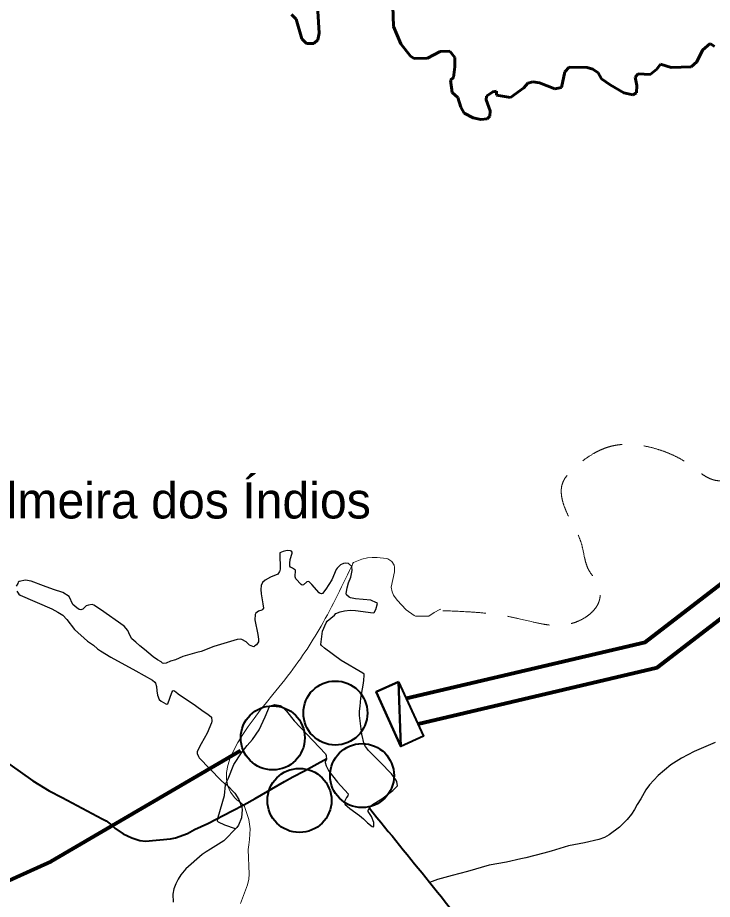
# Model space of a CAD drawing. Extents: x 553962 to 842807, y 8883888 to 9032388.
# Drawn here: x 756667 to 766307, y 8955756 to 8967998 of the extents above; entities that cross this region are included whole.
import ezdxf

# ---------------------------------------------------------------- set-up
doc = ezdxf.new("R2010")
doc.units = 0
doc.header["$LTSCALE"] = 200
doc.linetypes.add('LONG_DASH_SHORT_DASH', pattern=[9.9, 6, -1.2, 1.5, -1.2])
doc.linetypes.add('MEDIUM_DASHED', pattern=[4.5, 3, -1.5])
for name, color, linetype, lineweight in [('12', 7, 'Continuous', 25), ('14', 7, 'Continuous', 13), ('21', 7, 'Continuous', 25), ('28', 7, 'Continuous', 40), ('41', 7, 'Continuous', 40), ('7', 7, 'LONG_DASH_SHORT_DASH', 60)]:
    doc.layers.add(name, color=color, linetype=linetype, lineweight=lineweight)

msp = doc.modelspace()

# ---------------------------------------------------------------- linework, layer by layer
at = {"layer": '12', "lineweight": 40}
for points in [[(755751.2, 8958147.5), (755862.2, 8958064), (755958, 8957996.2), (756032.6, 8957954.2), (756137.7, 8957884), (756214, 8957842.6), (756328.1, 8957767.5), (756559.2, 8957627.5), (756879.8, 8957401.3), (757104, 8957264.6), (757287.1, 8957167.7), (757840.4, 8956875)], [(759805, 8957070.3), (759963.8, 8957157.4), (760368.2, 8957393.4), (760487, 8957457.4), (760649.4, 8957537.9), (760959, 8957710.3)], [(757840.4, 8956875), (757898, 8956844.5), (757957.3, 8956800.7), (758017.3, 8956746), (758132.8, 8956665.6), (758252.6, 8956612), (758364.7, 8956572), (758441.3, 8956562.7), (758786.4, 8956593.9), (758858.3, 8956611.9), (759022.3, 8956672.3), (759120.5, 8956724.4), (759308, 8956809.8), (759644.5, 8956982.5), (759805, 8957070.3)]]:
    msp.add_lwpolyline(points, dxfattribs=at)
at = {"layer": '12'}
for points in [[(766345.4, 8957933.7), (766056.1, 8957810.9), (766056.1, 8957810.9), (765878.8, 8957715.7), (765733, 8957623.3), (765557.2, 8957477.4), (765435.6, 8957344.7), (765384.6, 8957275.8), (765313.5, 8957149.9), (765262.4, 8957073.2), (765227, 8957004.6), (765185.1, 8956938.5), (765125.7, 8956864.1), (765018.7, 8956759.9), (764877.3, 8956651.4), (764811.5, 8956613.4), (764731.2, 8956586.7), (764533.1, 8956539.3), (764309.6, 8956500.2), (764071.8, 8956426.7)], [(759689.9, 8956732.7), (759543.3, 8956787), (759453.4, 8956827.9), (759441.1, 8956839.4), (759450.5, 8956898), (759538.2, 8957195.8), (759549.6, 8957346.3), (759553.3, 8957357.9), (759571, 8957344.3), (759680.6, 8957229.9), (759737, 8957142.1), (759777.6, 8957031.5), (759780.6, 8957004.8), (759774.7, 8956889.8), (759729.9, 8956785.1), (759706.9, 8956753.4), (759526.3, 8956568.6), (759344.8, 8956450.4), (759284.8, 8956417.4), (759226.1, 8956377.1), (758999, 8956178.4), (758931.1, 8956094.6), (758894, 8956037.2), (758861.3, 8955972.4), (758835.9, 8955899.8), (758821.1, 8955826.8), (758825.4, 8955718.1)], [(764071.8, 8956426.7), (763971, 8956395.5), (763720.5, 8956331.2), (763648.1, 8956319.8), (763449.9, 8956272.7), (763209, 8956229.3), (762911.9, 8956140.7), (762698.3, 8956084.6)], [(762698.3, 8956084.6), (762494.3, 8956031.1), (762382.1, 8955988.1)]]:
    msp.add_lwpolyline(points, dxfattribs=at)
at = {"layer": '12', "lineweight": 40}
msp.add_spline([(761549.2, 8957020.4), (762383.1, 8955993.9), (763257, 8954902.9), (764214.4, 8953717.3), (766168.2, 8951324.4), (767086.6, 8950171.6), (770317.8, 8946184.2), (771971, 8944146), (773006.3, 8942876.2), (773223.4, 8942642.3), (773373.7, 8942274.8), (774008.3, 8940921.5), (774359, 8940136.3), (774475.8, 8939919.1), (774642.8, 8939785.5), (774893.3, 8939668.5), (775511.2, 8939484.7), (775928.6, 8939267.5), (776078.9, 8939184), (776379.5, 8938916.7), (776680.1, 8938749.6), (776830.4, 8938582.6), (777398.1, 8938348.7), (777899.1, 8938231.7), (778550.4, 8938482.3), (779134.8, 8938866.6), (779452.1, 8939250.8), (779569, 8939384.5), (779685.9, 8939351.1), (779852.9, 8939217.4), (780086.7, 8939217.4), (780604.3, 8939451.3), (781055.2, 8939618.4), (781439.3, 8939618.4), (781823.3, 8939518.1), (782090.5, 8939401.2), (782290.9, 8939367.8), (782524.7, 8939518.1), (782858.7, 8939618.4), (783192.6, 8939651.8), (783509.9, 8939818.9), (783910.7, 8940119.6), (784278.1, 8940336.8), (784625.2, 8940434.5)], degree=3, dxfattribs=at)
at = {"layer": '14'}
for points in [[(762539, 8959785.5), (762526.5, 8959782.1), (762447.5, 8959737.2), (762371.9, 8959688.1), (762188, 8959687.4), (762169, 8959695.8), (762058.2, 8959775.3), (761932.6, 8959909.4), (761880.9, 8959981.3), (761863.6, 8960025), (761852.7, 8960090.2), (761896.3, 8960301.7), (761898.2, 8960370.1), (761891.8, 8960394.3), (761858.6, 8960446.3), (761803.1, 8960482.1), (761785, 8960487.6), (761657.6, 8960503.3), (761588.8, 8960503.3), (761520, 8960497.3), (761442.8, 8960481.4), (761326.7, 8960433.8), (761317.3, 8960424.7), (761303.1, 8960378.2)], [(759805, 8957070.3), (759809.7, 8957060.9), (759876.2, 8956866.7), (759896, 8956733.5), (759886, 8956587.7), (759873.4, 8956514.6), (759867.3, 8956445.9), (759879.8, 8956106.2), (759877.3, 8956037.4), (759858.6, 8955956.3), (759761.5, 8955697.4)]]:
    msp.add_lwpolyline(points, dxfattribs=at)
at = {"layer": '14', "linetype": 'MEDIUM_DASHED'}
msp.add_spline([(762566.7, 8959763.7), (763408.4, 8959695.8), (763753.5, 8959622.6), (764114.2, 8959559.8), (764542.9, 8959669.6), (764741.6, 8959915.3), (764720.7, 8960129.7), (764595.2, 8960323.1), (764490.6, 8960694.3), (764312.9, 8961070.7), (764229.2, 8961536), (764396.5, 8961750.3), (764929.8, 8962053.6), (765541.5, 8962006.5), (766027.7, 8961766), (766283.8, 8961593.5), (766466.8, 8961577.8), (766618.4, 8961776.5), (766670.7, 8962090.2), (766874.6, 8962247), (767287.6, 8962158.1), (767324.2, 8962132)], degree=3, dxfattribs=at)
at = {"layer": '14'}
msp.add_spline([(761326.7, 8960433.8), (760878.8, 8959550), (760374.9, 8958805.9), (759682, 8957166.3), (759809.7, 8957060.9)], degree=3, dxfattribs=at)
at = {"layer": '21'}
for points in [[(760406.9, 8960599.4), (760351.2, 8960587.4), (760306.3, 8960567.9), (760304.1, 8960553.3), (760309.9, 8960343.7), (760307.6, 8960319.4), (760302.3, 8960306.5), (760277, 8960272.3), (760173.9, 8960227.9), (760102, 8960186.9), (760066.3, 8960155.5), (760048.5, 8960114.9), (760043.8, 8960055.7), (760047.2, 8959999.8), (760070.9, 8959859.8), (760077.3, 8959796.6), (760071.9, 8959782.9), (760055.5, 8959771.5), (760010.4, 8959755.9), (759970.5, 8959727.7), (759962.7, 8959712), (759957.3, 8959636.2), (760000.3, 8959433.2), (760011.1, 8959366.6), (760007.5, 8959329.7), (759980.1, 8959288.4), (759957.5, 8959276), (759943.8, 8959263.8), (759943.8, 8959263.8), (759931.4, 8959264.6), (759884.8, 8959286.2), (759838.1, 8959329.8), (759780.4, 8959363), (759763.1, 8959366.1), (759715.1, 8959363.1), (759387.5, 8959268.5), (759215.8, 8959195.5), (759154.3, 8959182.2), (759089.3, 8959164.5)], [(761303.1, 8960378.2), (761256.6, 8960420.7), (761211, 8960424.4), (761189, 8960420), (761148.3, 8960398.4), (761101, 8960352.7), (761089.5, 8960334.7), (761027.1, 8960191.2), (760943.1, 8960062.8), (760896.2, 8960002.8), (760882, 8959997.4), (760865.7, 8960003.5), (760853.2, 8960013.2), (760749.8, 8960127.6), (760712.2, 8960164.5), (760701.2, 8960167.6), (760679.8, 8960164.2), (760632.4, 8960121), (760616.8, 8960117.8), (760603.7, 8960126.1), (760526.3, 8960205.6), (760516.4, 8960233.9), (760520.7, 8960327.1), (760483.2, 8960353), (760453.9, 8960367.2), (760443.7, 8960384.1), (760443.7, 8960422.2), (760450.8, 8960474.1), (760476.4, 8960562.9), (760474.8, 8960577.8), (760467.9, 8960589.4), (760454.3, 8960595.3), (760406.9, 8960599.4)], [(761456.2, 8958896.2), (761158.8, 8959073.4), (760923.1, 8959244.1), (760881.8, 8959278.4), (760874.4, 8959292.7), (760897, 8959480.3), (760948.2, 8959595.3), (760963.9, 8959617.7), (761063.1, 8959703.5), (761082.5, 8959724.5), (761142.1, 8959747.5), (761202.2, 8959763.2), (761279.4, 8959770.2), (761356.4, 8959765.7), (761602.1, 8959732.9), (761613.8, 8959740.5), (761636.1, 8959780.9), (761661.5, 8959862.7), (761646.6, 8959874.6), (761567.3, 8959909.9), (761356.6, 8959929.5), (761288, 8959941.5), (761269.3, 8959950.7), (761230.4, 8959983.8), (761227.4, 8960000.2), (761237.8, 8960082), (761258.1, 8960151), (761288.7, 8960228.4), (761310.4, 8960320.3), (761303.1, 8960378.2)], [(756667.8, 8960142.8), (756646.1, 8960103.2)], [(757025.3, 8960111), (756856.9, 8960173.6), (756774.4, 8960189), (756690.4, 8960169.5), (756676.8, 8960159.2), (756667.8, 8960142.8)], [(757384.3, 8959963), (757296.5, 8960017), (757165.6, 8960058.9), (757025.3, 8960111)], [(756655.4, 8960034.6), (756685.1, 8959993.4), (756700.1, 8959979.2), (757143.4, 8959788.8), (757225.5, 8959744.8), (757292.5, 8959702.4), (757351, 8959642), (757458.4, 8959500.5), (757638.5, 8959341.8), (757717.9, 8959284.2), (757774.1, 8959233.8), (757815.6, 8959204.4), (757958.2, 8959117.6), (758306, 8958929.9), (758539.4, 8958798.4), (758570.9, 8958770.5), (758581.6, 8958755.2), (758594, 8958710.9), (758597.7, 8958651.4), (758608.3, 8958591.8), (758630.7, 8958530.3), (758658.3, 8958506.6), (758722.6, 8958472.6), (758739.5, 8958467.4), (758749.1, 8958469.2), (758804.9, 8958627.7), (758819.6, 8958652.9), (758832.5, 8958653.7), (758862.6, 8958638.9), (758895.1, 8958607.2), (759137.6, 8958446.3), (759240.8, 8958367.8), (759305.9, 8958326.1), (759355.4, 8958284.4), (759361.1, 8958229.7), (759356.1, 8958207.5), (759296.4, 8958064.8), (759214.4, 8957916.7), (759160.7, 8957806.5), (759158.7, 8957795.2)], [(759089.3, 8959164.5), (758959.7, 8959128.9), (758856.5, 8959082.7), (758786.4, 8959061), (758729.8, 8959035.8), (758696.2, 8959030.6), (758679.5, 8959033.6), (758657.5, 8959052.8), (758608.3, 8959079.4), (758549.1, 8959121.3), (758427, 8959226.7), (758365.1, 8959274.5), (758308.6, 8959327.6), (758250.8, 8959371), (758222.4, 8959421.7), (758194.1, 8959488.8), (758147.7, 8959547.5), (757819.2, 8959780.1), (757726.2, 8959841.5), (757701.7, 8959847.4), (757651.1, 8959840.7), (757620.3, 8959829.3), (757571.8, 8959784.6), (757543.6, 8959777.7), (757522.3, 8959779.8), (757486.6, 8959802), (757431.8, 8959850.2), (757384.3, 8959963)], [(761460.2, 8958729), (761471.4, 8958793.2), (761478, 8958868), (761475.3, 8958881.2), (761456.2, 8958896.2)], [(761699.8, 8957660.8), (761534.4, 8957820.5), (761494.3, 8957876.1), (761476.7, 8957908.7), (761441.7, 8958050.3), (761410.2, 8958307.4), (761410.3, 8958367.7), (761421.6, 8958439.5), (761428.9, 8958549.5), (761460.2, 8958729)], [(759588.1, 8957430.5), (759665.6, 8957627.1), (759774.1, 8957789.3), (759851, 8957889.6), (759926.4, 8957977.2), (760019.3, 8958109.5), (760103.6, 8958290.5), (760163.1, 8958434.3), (760177, 8958444.1), (760236, 8958459.9), (760236, 8958459.9), (760311.5, 8958445.7), (760328.1, 8958437.3), (760399.4, 8958368.9), (760505.5, 8958234.5), (760941.1, 8957774.4), (760949.2, 8957754.5), (760953.1, 8957699.6), (760934.3, 8957666.8), (760932.5, 8957654.1), (760946.9, 8957611.2), (760983.8, 8957536.8), (761107.8, 8957384.2), (761255, 8957220.4), (761250.7, 8957192.7), (761230.3, 8957168.3), (761203.2, 8957115.4), (761200.8, 8957095.3), (761208, 8957075.8), (761277.5, 8957017.6), (761412.8, 8956919.4), (761466, 8956875.3), (761523.6, 8956817.2), (761588.2, 8956767.8), (761600.9, 8956762.8), (761607.8, 8956766.9), (761610.8, 8956824.1), (761578.4, 8956906.9), (761533.3, 8956976.3), (761532.5, 8956989.4), (761545, 8957020.8), (761589.6, 8957073.6), (761719.9, 8957149.7), (761874.4, 8957269.1), (761925.5, 8957315.7), (761936.7, 8957332.9), (761927.8, 8957389.9), (761916.5, 8957416.7), (761854.4, 8957499), (761699.8, 8957660.8)], [(759158.7, 8957795.2), (759156.5, 8957782.8), (759174.7, 8957739.3), (759187.4, 8957722), (759486.6, 8957410.7), (759541.3, 8957360.2), (759547, 8957358.6), (759554, 8957364.5), (759569.1, 8957391.3), (759588.1, 8957430.5)]]:
    msp.add_lwpolyline(points, dxfattribs=at)
at = {"layer": '28', "lineweight": 80}
for p, q in [((759759.2, 8957818.1), (757134.6, 8956280.5)), ((757134.6, 8956280.5), (754888.4, 8955266.6))]:
    msp.add_line(p, q, dxfattribs=at)
for points in [[(762063.2, 8958548.7), (765372.8, 8959328.2), (767563.5, 8961012.7), (769365.7, 8961826.5), (770195.5, 8963207.4)], [(762225.3, 8958192.4), (765541.3, 8958973.5), (767762.1, 8960681.2), (769633, 8961525.9), (770439.4, 8962868)]]:
    msp.add_lwpolyline(points, dxfattribs=at)
at = {"layer": '28'}
msp.add_lwpolyline([(761954, 8958776.7), (762297, 8958021.1), (761985.7, 8957879.8), (761642.7, 8958635.3)], close=True, dxfattribs=at)
for points in [[(761954, 8958776.7), (761642.7, 8958635.3), (761985.7, 8957879.8)], [(761954, 8958776.7), (761985.7, 8957879.8), (761954, 8958776.7)]]:
    msp.add_lwpolyline(points, dxfattribs=at)
for centre in [(761076.3, 8958343), (760207.7, 8957997.9), (761446.7, 8957473.9), (760578.1, 8957128.8)]:
    msp.add_circle(centre, 444.4, dxfattribs=at)
at = {"layer": '7'}
for points in [[(760468.7, 8968041.8), (760531.4, 8967975.3), (760612.4, 8967703.8), (760676.7, 8967637.3), (760778.2, 8967637.3), (760833.4, 8967688.2), (760853, 8967781.7), (760833.6, 8968087.2)], [(761875.3, 8968158.2), (761883.2, 8967876.5), (761983, 8967632.3), (762120.3, 8967463.7), (762171.6, 8967432.4), (762355.5, 8967436.4), (762528.1, 8967526.2), (762662.3, 8967534.7), (762735.1, 8967446.8), (762735.2, 8967316.2), (762713.7, 8967168.6), (762672.7, 8967130.8), (762696.2, 8966959), (762775.9, 8966891.5), (762816.7, 8966756.5), (762864.1, 8966670.5)], [(762864.1, 8966670.5), (762988, 8966606.5), (762988, 8966606.5), (763095.2, 8966585), (763183.7, 8966590.9), (763219.9, 8966628.1), (763224.1, 8966703.1), (763170.7, 8966857.1), (763174.8, 8966906), (763262.9, 8966969), (763309.8, 8966977.2), (763310.4, 8966921.6), (763507.9, 8966888.4), (763691, 8967024.3), (763748, 8967090.2), (763816.6, 8967107.8), (763910.7, 8967092.2), (764122.4, 8967010.1), (764212.2, 8967029.6), (764259.7, 8967244.8), (764318.7, 8967311.3), (764570.8, 8967305.5), (764649.7, 8967281.9), (764724.1, 8967231), (764771.2, 8967149), (764888.8, 8967062.9), (765079, 8966955.3), (765204.4, 8966928), (765255.2, 8966955.3), (765259.2, 8967057), (765236, 8967169.9), (765276.9, 8967219.6), (765446.1, 8967207), (765538.2, 8967283.2), (765589.3, 8967353.4), (765738, 8967305.5), (766013.4, 8967316.3), (766092, 8967385.3), (766172.2, 8967546), (766278, 8967639.8), (766338.4, 8967596.9)], [(762864.1, 8966670.5), (762988, 8966606.5), (762988, 8966606.5), (763095.2, 8966585), (763183.7, 8966590.9), (763219.9, 8966628.1), (763224.1, 8966703.1), (763170.7, 8966857.1), (763174.8, 8966906), (763262.9, 8966969), (763309.8, 8966977.2), (763310.4, 8966921.6), (763507.9, 8966888.4), (763691, 8967024.3), (763748, 8967090.2), (763816.6, 8967107.8), (763910.7, 8967092.2), (764122.4, 8967010.1), (764212.2, 8967029.6), (764259.7, 8967244.8), (764318.7, 8967311.3), (764570.8, 8967305.5), (764649.7, 8967281.9), (764724.1, 8967231), (764771.2, 8967149), (764888.8, 8967062.9), (765079, 8966955.3), (765204.4, 8966928), (765255.2, 8966955.3), (765259.2, 8967057), (765236, 8967169.9), (765276.9, 8967219.6), (765446.1, 8967207), (765538.2, 8967283.2), (765589.3, 8967353.4), (765738, 8967305.5), (766013.4, 8967316.3), (766092, 8967385.3), (766172.2, 8967546), (766278, 8967639.8), (766338.4, 8967596.9)]]:
    msp.add_lwpolyline(points, dxfattribs=at)

# ---------------------------------------------------------------- texts
at = {"layer": '41'}
msp.add_text('Palmeira dos Índios', height=500, dxfattribs=at).set_placement((755696.3, 8961044.2))

doc.saveas('drawing.dxf')
